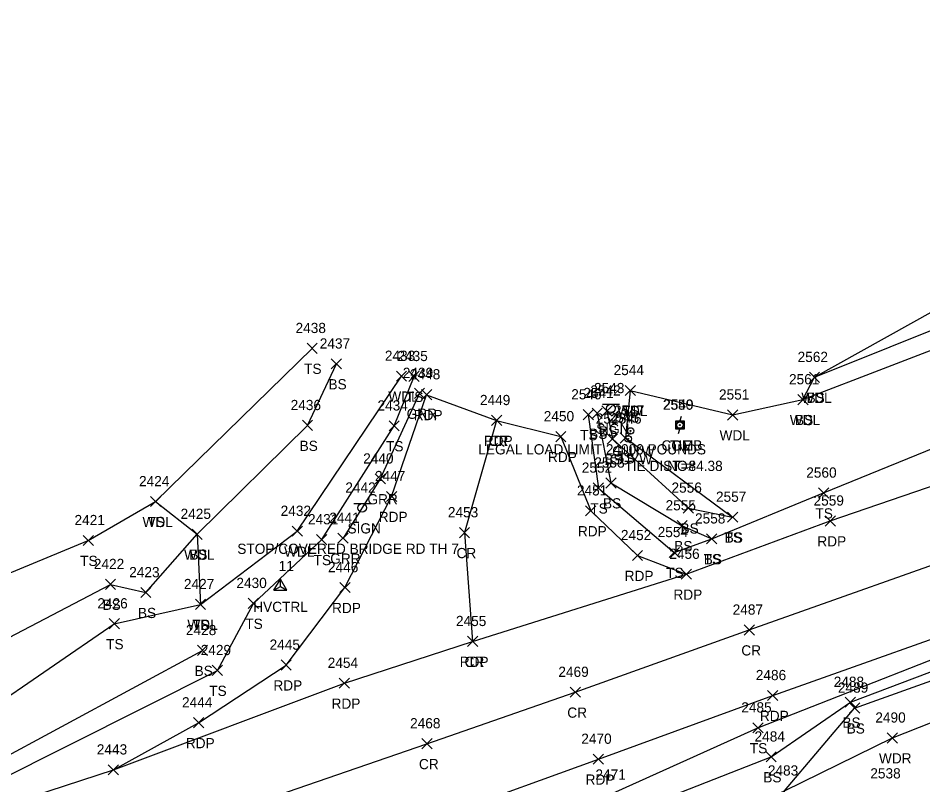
# Model space of a CAD drawing. Extents: x 1699408 to 1700423, y 840176 to 841410.
# Drawn here: x 1700025.1 to 1700202.3, y 840401 to 840551.2 of the extents above; entities that cross this region are included whole.
import ezdxf

# ---------------------------------------------------------------- set-up
doc = ezdxf.new("R2010")
doc.units = 0
for name, color, linetype in [('C_A', 7, 'Continuous'), ('C_C', 7, 'Continuous'), ('C_I', 7, 'Continuous'), ('CBP', 7, 'Continuous'), ('CPSM', 7, 'Continuous'), ('L_A', 7, 'Continuous'), ('L_I', 7, 'Continuous'), ('L_TIC', 7, 'Continuous'), ('LAWA', 7, 'Continuous'), ('LELB', 7, 'Continuous'), ('P_A', 7, 'Continuous'), ('P_I', 7, 'Continuous'), ('P_TIC', 7, 'Continuous'), ('PET', 7, 'Continuous'), ('PRC', 7, 'Continuous'), ('R_A', 7, 'Continuous'), ('R_I', 7, 'Continuous'), ('R_TIC', 7, 'Continuous'), ('RGR', 7, 'Continuous'), ('S_A', 7, 'Continuous'), ('S_C', 7, 'Continuous'), ('S_I', 7, 'Continuous'), ('SSGN', 7, 'Continuous'), ('U_A', 7, 'Continuous'), ('U_C', 7, 'Continuous'), ('U_I', 7, 'Continuous'), ('UP', 7, 'Continuous'), ('UPGW', 7, 'Continuous')]:
    doc.layers.add(name, color=color, linetype=linetype)

msp = doc.modelspace()

# ---------------------------------------------------------------- linework, layer by layer
at = {"layer": 'CBP'}
for radius in [0.625, 0.0833]:
    msp.add_circle((1700154.75, 840471.45), radius, dxfattribs=at)
at = {"layer": 'CPSM'}
for p, q in [((1700075.25, 840439.12), (1700076.5, 840441.29)), ((1700077.75, 840439.12), (1700076.5, 840441.29)), ((1700076.5, 840439.85), (1700076.5, 840441.29)), ((1700075.25, 840439.12), (1700076.5, 840439.85)), ((1700075.25, 840439.12), (1700077.75, 840439.12)), ((1700076.5, 840439.85), (1700076.5, 840439.85)), ((1700076.5, 840439.85), (1700077.75, 840439.12))]:
    msp.add_line(p, q, dxfattribs=at)
at = {"layer": 'L_TIC'}
for points in [[(1700081.74, 840485.47), (1700083.74, 840487.47)], [(1700083.74, 840485.47), (1700081.74, 840487.47)], [(1700086.48, 840482.44), (1700088.48, 840484.44)], [(1700088.48, 840482.44), (1700086.48, 840484.44)], [(1700099.23, 840480.03), (1700101.23, 840482.03)], [(1700101.23, 840480.03), (1700099.23, 840482.03)], [(1700101.69, 840479.98), (1700103.69, 840481.98)], [(1700103.69, 840479.98), (1700101.69, 840481.98)], [(1700180.12, 840479.8), (1700182.12, 840481.8)], [(1700182.12, 840479.8), (1700180.12, 840481.8)], [(1700180.12, 840479.8), (1700182.12, 840481.8)], [(1700182.12, 840479.8), (1700180.12, 840481.8)], [(1700144.03, 840477.23), (1700146.03, 840479.23)], [(1700146.03, 840477.23), (1700144.03, 840479.23)], [(1700144.03, 840477.23), (1700146.03, 840479.23)], [(1700146.03, 840477.23), (1700144.03, 840479.23)], [(1700177.86, 840475.43), (1700179.86, 840477.43)], [(1700179.86, 840475.43), (1700177.86, 840477.43)], [(1700177.86, 840475.43), (1700179.86, 840477.43)], [(1700179.86, 840475.43), (1700177.86, 840477.43)], [(1700135.81, 840472.48), (1700137.81, 840474.48)], [(1700137.81, 840472.48), (1700135.81, 840474.48)], [(1700137.54, 840472.74), (1700139.54, 840474.74)], [(1700139.54, 840472.74), (1700137.54, 840474.74)], [(1700139.47, 840473.22), (1700141.47, 840475.22)], [(1700141.47, 840473.22), (1700139.47, 840475.22)], [(1700164.1, 840472.44), (1700166.1, 840474.44)], [(1700166.1, 840472.44), (1700164.1, 840474.44)], [(1700080.83, 840470.38), (1700082.83, 840472.38)], [(1700082.83, 840470.38), (1700080.83, 840472.38)], [(1700097.79, 840470.3), (1700099.79, 840472.3)], [(1700099.79, 840470.3), (1700097.79, 840472.3)], [(1700140.53, 840467.73), (1700142.53, 840469.73)], [(1700142.53, 840467.73), (1700140.53, 840469.73)], [(1700143.08, 840467.93), (1700145.08, 840469.93)], [(1700145.08, 840467.93), (1700143.08, 840469.93)], [(1700140.25, 840459.12), (1700142.25, 840461.12)], [(1700142.25, 840459.12), (1700140.25, 840461.12)], [(1700137.8, 840458.12), (1700139.8, 840460.12)], [(1700139.8, 840458.12), (1700137.8, 840460.12)], [(1700181.9, 840457.15), (1700183.9, 840459.15)], [(1700183.9, 840457.15), (1700181.9, 840459.15)], [(1700051.08, 840455.47), (1700053.08, 840457.47)], [(1700053.08, 840455.47), (1700051.08, 840457.47)], [(1700051.08, 840455.47), (1700053.08, 840457.47)], [(1700053.08, 840455.47), (1700051.08, 840457.47)], [(1700155.42, 840454.2), (1700157.42, 840456.2)], [(1700157.42, 840454.2), (1700155.42, 840456.2)], [(1700164.08, 840452.42), (1700166.08, 840454.42)], [(1700166.08, 840452.42), (1700164.08, 840454.42)], [(1700164.08, 840452.42), (1700166.08, 840454.42)], [(1700166.08, 840452.42), (1700164.08, 840454.42)], [(1700078.82, 840449.67), (1700080.82, 840451.67)], [(1700080.82, 840449.67), (1700078.82, 840451.67)], [(1700154.21, 840450.74), (1700156.21, 840452.74)], [(1700156.21, 840450.74), (1700154.21, 840452.74)], [(1700037.88, 840447.85), (1700039.88, 840449.85)], [(1700039.88, 840447.85), (1700037.88, 840449.85)], [(1700059.22, 840449.07), (1700061.22, 840451.07)], [(1700061.22, 840449.07), (1700059.22, 840451.07)], [(1700059.22, 840449.07), (1700061.22, 840451.07)], [(1700061.22, 840449.07), (1700059.22, 840451.07)], [(1700083.61, 840448.01), (1700085.61, 840450.01)], [(1700085.61, 840448.01), (1700083.61, 840450.01)], [(1700159.98, 840448.17), (1700161.98, 840450.17)], [(1700161.98, 840448.17), (1700159.98, 840450.17)], [(1700159.98, 840448.17), (1700161.98, 840450.17)], [(1700161.98, 840448.17), (1700159.98, 840450.17)], [(1700152.66, 840445.5), (1700154.66, 840447.5)], [(1700154.66, 840445.5), (1700152.66, 840447.5)], [(1700042.23, 840439.25), (1700044.23, 840441.25)], [(1700044.23, 840439.25), (1700042.23, 840441.25)], [(1700049.16, 840437.65), (1700051.16, 840439.65)], [(1700051.16, 840437.65), (1700049.16, 840439.65)], [(1700059.87, 840435.32), (1700061.87, 840437.32)], [(1700061.87, 840435.32), (1700059.87, 840437.32)], [(1700059.87, 840435.32), (1700061.87, 840437.32)], [(1700061.87, 840435.32), (1700059.87, 840437.32)], [(1700070.23, 840435.53), (1700072.23, 840437.53)], [(1700072.23, 840435.53), (1700070.23, 840437.53)], [(1700042.97, 840431.54), (1700044.97, 840433.54)], [(1700044.97, 840431.54), (1700042.97, 840433.54)], [(1700060.26, 840426.31), (1700062.26, 840428.31)], [(1700062.26, 840426.31), (1700060.26, 840428.31)], [(1700063.16, 840422.4), (1700065.16, 840424.4)], [(1700065.16, 840422.4), (1700063.16, 840424.4)], [(1700187.14, 840416.18), (1700189.14, 840418.18)], [(1700189.14, 840416.18), (1700187.14, 840418.18)], [(1700187.97, 840415.03), (1700189.97, 840417.03)], [(1700189.97, 840415.03), (1700187.97, 840417.03)], [(1700169.04, 840411.16), (1700171.04, 840413.16)], [(1700171.04, 840411.16), (1700169.04, 840413.16)], [(1700195.37, 840409.18), (1700197.37, 840411.18)], [(1700197.37, 840409.18), (1700195.37, 840411.18)], [(1700171.64, 840405.47), (1700173.64, 840407.47)], [(1700173.64, 840405.47), (1700171.64, 840407.47)]]:
    msp.add_lwpolyline(points, dxfattribs=at)
at = {"layer": 'LAWA'}
for points in [[(1700145.03, 840478.23), (1700165.1, 840473.44), (1700178.86, 840476.43), (1700181.12, 840480.8), (1700209.13, 840496.46), (1700243.79, 840518.11), (1700281.69, 840520.84), (1700332.18, 840533.79), (1700369.71, 840547.2), (1700395.55, 840551.16)], [(1700117.89, 840346.79), (1700115.47, 840370.34), (1700134.74, 840381.65), (1700175.24, 840399.81), (1700196.37, 840410.18), (1700227.82, 840422.6), (1700263.02, 840437.63), (1700310.41, 840452.18), (1700348.89, 840465.62), (1700387.69, 840477.37), (1700417.82, 840485.58)], [(1700052.08, 840456.47), (1700060.22, 840450.07), (1700060.87, 840436.32), (1700079.82, 840450.67), (1700100.23, 840481.03)]]:
    msp.add_lwpolyline(points, dxfattribs=at)
at = {"layer": 'LELB'}
for points in [[(1700181.12, 840480.8), (1700210.79, 840492.71), (1700248.16, 840507.11), (1700281.22, 840518.3), (1700334.33, 840530.5), (1700370.69, 840544.36), (1700395.55, 840551.16)], [(1700178.86, 840476.43), (1700212.16, 840489.26), (1700248.63, 840504.95), (1700282.26, 840515.64), (1700334.86, 840528.51), (1700371.4, 840540.85), (1700398.24, 840544.25)], [(1700136.81, 840473.48), (1700138.8, 840459.12), (1700153.66, 840446.5), (1700160.98, 840449.17), (1700182.9, 840458.15), (1700217.68, 840472.32), (1700251.63, 840484.37), (1700288.96, 840496.07), (1700338.68, 840513.45), (1700373.92, 840524.16), (1700400.76, 840534.56)], [(1699894.91, 840318.62), (1699909.54, 840320.37), (1699931.73, 840326.89), (1699942.77, 840330.34), (1699953.04, 840332.24), (1699965.49, 840337.33), (1699971.91, 840344.73), (1700003.63, 840352.88), (1700032.87, 840363), (1700063.25, 840372.76), (1700109.93, 840390.42), (1700140.91, 840399), (1700170.04, 840412.16), (1700222.58, 840432.8), (1700261.59, 840445.7), (1700307.68, 840461.11), (1700347.68, 840474.56), (1700384.18, 840486.92), (1700414.06, 840495.99)], [(1699950.19, 840322.46), (1699970.52, 840330.95), (1699975.9, 840338.67), (1700003.21, 840345.94), (1700034.35, 840356.49), (1700066.22, 840366.04), (1700111.96, 840382.71), (1700172.64, 840406.47), (1700188.14, 840417.18), (1700223.53, 840430.55), (1700261.76, 840444.29), (1700308.01, 840458.93), (1700347.92, 840472.31), (1700385.46, 840483.48), (1700416.04, 840491.19)], [(1700177.27, 840387.2), (1700175.24, 840399.81), (1700188.97, 840416.03), (1700224.35, 840428.66), (1700261.3, 840441.34), (1700309.36, 840456.05), (1700348.46, 840469.98), (1700386.66, 840479.73), (1700417.03, 840487.78)], [(1699978.99, 840419.52), (1699997.35, 840429.46), (1700012, 840437.76), (1700038.88, 840448.85), (1700052.08, 840456.47), (1700082.74, 840486.47)], [(1699973.36, 840411.5), (1700000.19, 840415.42), (1700014.72, 840425.34), (1700043.23, 840440.25), (1700050.16, 840438.65), (1700060.22, 840450.07), (1700081.83, 840471.38), (1700087.48, 840483.44)], [(1699979.47, 840387.15), (1700008.42, 840397.8), (1700020.57, 840401.5), (1700064.16, 840423.4), (1700071.23, 840436.53), (1700084.61, 840449.01), (1700098.79, 840471.3), (1700102.69, 840480.98)], [(1700145.03, 840478.23), (1700144.08, 840468.93), (1700165.08, 840453.42)], [(1700138.54, 840473.74), (1700141.25, 840460.12), (1700155.21, 840451.74), (1700160.98, 840449.17)], [(1700140.47, 840474.22), (1700141.53, 840468.73), (1700156.42, 840455.2), (1700165.08, 840453.42)], [(1699946.19, 840397.92), (1699957.68, 840405.42), (1699965.5, 840411.31), (1699969.56, 840405.36), (1699976.97, 840400.87), (1700003.92, 840408.68), (1700018.42, 840415.01), (1700043.97, 840432.54), (1700060.87, 840436.32)], [(1699969.68, 840389.69), (1700006.32, 840402.67), (1700019.85, 840404.95), (1700061.26, 840427.31)]]:
    msp.add_lwpolyline(points, dxfattribs=at)
at = {"layer": 'P_TIC'}
for points in [[(1700104.14, 840476.4), (1700106.14, 840478.4)], [(1700106.14, 840476.4), (1700104.14, 840478.4)], [(1700117.86, 840471.36), (1700119.86, 840473.36)], [(1700119.86, 840471.36), (1700117.86, 840473.36)], [(1700117.86, 840471.36), (1700119.86, 840473.36)], [(1700119.86, 840471.36), (1700117.86, 840473.36)], [(1700130.44, 840468.19), (1700132.44, 840470.19)], [(1700132.44, 840468.19), (1700130.44, 840470.19)], [(1700097.29, 840456.47), (1700099.29, 840458.47)], [(1700099.29, 840456.47), (1700097.29, 840458.47)], [(1700136.28, 840453.66), (1700138.28, 840455.66)], [(1700138.28, 840453.66), (1700136.28, 840455.66)], [(1700183.2, 840451.68), (1700185.2, 840453.68)], [(1700185.2, 840451.68), (1700183.2, 840453.68)], [(1700111.57, 840449.38), (1700113.57, 840451.38)], [(1700113.57, 840449.38), (1700111.57, 840451.38)], [(1700145.46, 840444.91), (1700147.46, 840446.91)], [(1700147.46, 840444.91), (1700145.46, 840446.91)], [(1700155, 840441.24), (1700157, 840443.24)], [(1700157, 840441.24), (1700155, 840443.24)], [(1700155, 840441.24), (1700157, 840443.24)], [(1700157, 840441.24), (1700155, 840443.24)], [(1700088.15, 840438.63), (1700090.15, 840440.63)], [(1700090.15, 840438.63), (1700088.15, 840440.63)], [(1700167.35, 840430.32), (1700169.35, 840432.32)], [(1700169.35, 840430.32), (1700167.35, 840432.32)], [(1700113.15, 840428.08), (1700115.15, 840430.08)], [(1700115.15, 840428.08), (1700113.15, 840430.08)], [(1700113.15, 840428.08), (1700115.15, 840430.08)], [(1700115.15, 840428.08), (1700113.15, 840430.08)], [(1700076.65, 840423.45), (1700078.65, 840425.45)], [(1700078.65, 840423.45), (1700076.65, 840425.45)], [(1700088.04, 840419.89), (1700090.04, 840421.89)], [(1700090.04, 840419.89), (1700088.04, 840421.89)], [(1700133.27, 840418.13), (1700135.27, 840420.13)], [(1700135.27, 840418.13), (1700133.27, 840420.13)], [(1700171.93, 840417.49), (1700173.93, 840419.49)], [(1700173.93, 840417.49), (1700171.93, 840419.49)], [(1700059.5, 840412.15), (1700061.5, 840414.15)], [(1700061.5, 840412.15), (1700059.5, 840414.15)], [(1700104.22, 840408.05), (1700106.22, 840410.05)], [(1700106.22, 840408.05), (1700104.22, 840410.05)], [(1700137.79, 840405.02), (1700139.79, 840407.02)], [(1700139.79, 840405.02), (1700137.79, 840407.02)], [(1700042.81, 840402.93), (1700044.81, 840404.93)], [(1700044.81, 840402.93), (1700042.81, 840404.93)], [(1700042.81, 840402.93), (1700044.81, 840404.93)], [(1700044.81, 840402.93), (1700042.81, 840404.93)]]:
    msp.add_lwpolyline(points, dxfattribs=at)
at = {"layer": 'PET'}
for points in [[(1700021.62, 840396.71), (1700043.81, 840403.93), (1700089.04, 840420.89), (1700114.15, 840429.08), (1700156, 840442.24), (1700184.2, 840452.68), (1700219.84, 840464.9), (1700253.86, 840476.91), (1700292.78, 840490.43), (1700340.75, 840506.36), (1700375.21, 840518.2), (1700402.6, 840527.14)], [(1700000.7, 840359.42), (1700031.35, 840369.03), (1700061.33, 840378.61), (1700109.24, 840395.28), (1700138.79, 840406.02), (1700172.93, 840418.49), (1700221.46, 840435.72), (1700260.32, 840448.69), (1700306.34, 840464.7), (1700346.69, 840478.05), (1700382.8, 840490.67), (1700413.01, 840500.61)], [(1700043.81, 840403.93), (1700060.5, 840413.15), (1700077.65, 840424.45), (1700089.15, 840439.63), (1700098.29, 840457.47), (1700105.14, 840477.4), (1700118.86, 840472.36), (1700131.44, 840469.19), (1700137.28, 840454.66), (1700146.46, 840445.91), (1700156, 840442.24)]]:
    msp.add_lwpolyline(points, dxfattribs=at)
at = {"layer": 'PRC'}
for points in [[(1699996.81, 840372.51), (1700026.94, 840382.38), (1700056.52, 840392.21), (1700105.22, 840409.05), (1700134.27, 840419.13), (1700168.35, 840431.32), (1700216.93, 840448.55), (1700256.68, 840462.13), (1700302.17, 840477.7), (1700342.85, 840491.54), (1700378.3, 840503.62), (1700408.52, 840513.62)], [(1700118.86, 840472.36), (1700112.57, 840450.38), (1700114.15, 840429.08)]]:
    msp.add_lwpolyline(points, dxfattribs=at)
at = {"layer": 'R_TIC'}
for points in [[(1700102.75, 840476.67), (1700104.75, 840478.67)], [(1700104.75, 840476.67), (1700102.75, 840478.67)], [(1700095.07, 840459.92), (1700097.07, 840461.92)], [(1700097.07, 840459.92), (1700095.07, 840461.92)], [(1700087.78, 840448.3), (1700089.78, 840450.3)], [(1700089.78, 840448.3), (1700087.78, 840450.3)]]:
    msp.add_lwpolyline(points, dxfattribs=at)
at = {"layer": 'RGR'}
msp.add_lwpolyline([(1700103.75, 840477.67), (1700096.07, 840460.92), (1700088.78, 840449.3)], dxfattribs=at)
at = {"layer": 'SSGN'}
for p, q in [((1700139.57, 840475.55), (1700142.91, 840475.55)), ((1700141.22, 840474.72), (1700141.22, 840474.72)), ((1700090.87, 840456.08), (1700094.2, 840456.08)), ((1700092.51, 840455.24), (1700092.51, 840455.24))]:
    msp.add_line(p, q, dxfattribs=at)
for centre in [(1700141.22, 840474.72), (1700092.51, 840455.24)]:
    msp.add_circle(centre, 0.833, dxfattribs=at)
at = {"layer": 'UP'}
for p, q in [((1700155.01, 840473.13), (1700154.76, 840472.3)), ((1700153.93, 840470.63), (1700153.93, 840472.3)), ((1700153.93, 840472.3), (1700155.59, 840472.3)), ((1700154.76, 840471.46), (1700154.76, 840471.46)), ((1700155.59, 840472.3), (1700155.59, 840470.63)), ((1700155.59, 840470.63), (1700153.93, 840470.63)), ((1700154.51, 840469.8), (1700154.76, 840470.63))]:
    msp.add_line(p, q, dxfattribs=at)
msp.add_circle((1700154.76, 840471.46), 0.833, dxfattribs=at)
at = {"layer": 'UPGW'}
for centre, radius in [((1700145.1, 840470.3), 0.625), ((1700144.62, 840468.74), 0.625), ((1700145.1, 840470.3), 0.0833), ((1700144.62, 840468.74), 0.0833)]:
    msp.add_circle(centre, radius, dxfattribs=at)

# ---------------------------------------------------------------- texts
at = {"layer": 'C_A'}
for s, p in [('TIE', (1700152.83, 840466.45)), ('HVCTRL', (1700071.19, 840434.85))]:
    msp.add_text(s, height=2, dxfattribs=at).set_placement(p)
at = {"layer": 'C_C'}
msp.add_text('TIE DIST=84.38', height=2, dxfattribs=at).set_placement((1700143.89, 840462.45))
at = {"layer": 'C_I'}
for s, p in [('2550', (1700151.41, 840474.45)), ('11', (1700076.17, 840442.85))]:
    msp.add_text(s, height=2, dxfattribs=at).set_placement(p)
at = {"layer": 'L_A'}
for s, p in [('TS', (1700081.15, 840481.47)), ('BS', (1700085.92, 840478.44)), ('WDL', (1700097.65, 840476.03)), ('TS', (1700101.1, 840475.98)), ('WDL', (1700178.54, 840475.8)), ('BS', (1700179.56, 840475.8)), ('WDL', (1700142.45, 840473.23)), ('TS', (1700143.44, 840473.23)), ('WDL', (1700176.28, 840471.43)), ('BS', (1700177.3, 840471.43)), ('BS', (1700136.98, 840468.74)), ('BS', (1700138.91, 840469.22)), ('TS', (1700135.22, 840468.48)), ('WDL', (1700162.52, 840468.44)), ('BS', (1700080.27, 840466.38)), ('TS', (1700097.2, 840466.3)), ('BS', (1700139.97, 840463.73)), ('TS', (1700142.49, 840463.93)), ('BS', (1700139.69, 840455.12)), ('TS', (1700137.21, 840454.12)), ('TS', (1700181.3, 840453.15)), ('WDL', (1700049.5, 840451.47)), ('TS', (1700050.49, 840451.47)), ('BS', (1700154.87, 840450.2)), ('TS', (1700163.49, 840448.42)), ('BS', (1700163.53, 840448.42)), ('BS', (1700153.65, 840446.74)), ('WDL', (1700057.64, 840445.07)), ('BS', (1700058.66, 840445.07)), ('WDL', (1700077.24, 840445.67)), ('TS', (1700083.01, 840444.01)), ('TS', (1700159.39, 840444.17)), ('BS', (1700159.42, 840444.17)), ('TS', (1700037.29, 840443.85)), ('TS', (1700152.07, 840441.5)), ('BS', (1700041.68, 840435.25)), ('BS', (1700048.6, 840433.65)), ('TS', (1700069.64, 840431.53)), ('WDL', (1700058.29, 840431.32)), ('TS', (1700059.28, 840431.32)), ('TS', (1700042.38, 840427.54)), ('BS', (1700059.7, 840422.31)), ('TS', (1700062.57, 840418.4)), ('BS', (1700186.58, 840412.18)), ('BS', (1700187.41, 840411.03)), ('TS', (1700168.45, 840407.16)), ('WDR', (1700193.74, 840405.18)), ('BS', (1700171.09, 840401.47))]:
    msp.add_text(s, height=2, dxfattribs=at).set_placement(p)
at = {"layer": 'L_I'}
for s, p in [('2438', (1700079.48, 840489.47)), ('2437', (1700084.22, 840486.44)), ('2433', (1700096.97, 840484.03)), ('2435', (1700099.43, 840483.98)), ('2562', (1700177.81, 840483.8)), ('2562', (1700177.81, 840483.8)), ('2544', (1700141.77, 840481.23)), ('2544', (1700141.77, 840481.23)), ('2561', (1700176.12, 840479.43)), ('2561', (1700176.12, 840479.43)), ('2540', (1700133.47, 840476.48)), ('2541', (1700135.84, 840476.74)), ('2542', (1700137.21, 840477.22)), ('2551', (1700162.41, 840476.44)), ('2436', (1700078.52, 840474.38)), ('2434', (1700095.53, 840474.3)), ('2548', (1700138.27, 840471.73)), ('2545', (1700140.82, 840471.93)), ('2552', (1700135.54, 840462.12)), ('2553', (1700137.99, 840463.12)), ('2560', (1700179.5, 840461.15)), ('2424', (1700048.82, 840459.47)), ('2424', (1700048.82, 840459.47)), ('2556', (1700153.11, 840458.2)), ('2557', (1700161.82, 840456.42)), ('2557', (1700161.82, 840456.42)), ('2555', (1700151.95, 840454.74)), ('2425', (1700056.96, 840453.07)), ('2425', (1700056.96, 840453.07)), ('2432', (1700076.56, 840453.67)), ('2421', (1700036.18, 840451.85)), ('2431', (1700081.91, 840452.01)), ('2558', (1700157.72, 840452.17)), ('2558', (1700157.72, 840452.17)), ('2554', (1700150.4, 840449.5)), ('2422', (1700039.97, 840443.25)), ('2423', (1700046.9, 840441.65)), ('2427', (1700057.61, 840439.32)), ('2427', (1700057.61, 840439.32)), ('2430', (1700067.89, 840439.53)), ('2426', (1700040.66, 840435.54)), ('2428', (1700058, 840430.31)), ('2429', (1700060.9, 840426.4)), ('2488', (1700184.88, 840420.18)), ('2489', (1700185.7, 840419.03)), ('2485', (1700166.78, 840415.16)), ('2490', (1700193.03, 840413.18)), ('2484', (1700169.38, 840409.47)), ('2471', (1700138.21, 840402)), ('2483', (1700171.98, 840402.81)), ('2483', (1700171.98, 840402.81)), ('2538', (1700192.05, 840402.24))]:
    msp.add_text(s, height=2, dxfattribs=at).set_placement(p)
at = {"layer": 'P_A'}
for s, p in [('RDP', (1700102.63, 840472.4)), ('RDP', (1700116.35, 840467.36)), ('CR', (1700117.29, 840467.36)), ('RDP', (1700128.92, 840464.19)), ('RDP', (1700095.77, 840452.47)), ('RDP', (1700134.77, 840449.66)), ('RDP', (1700181.68, 840447.68)), ('CR', (1700111, 840445.38)), ('RDP', (1700143.94, 840440.91)), ('RDP', (1700153.49, 840437.24)), ('RDP', (1700153.49, 840437.24)), ('RDP', (1700086.63, 840434.63)), ('CR', (1700166.79, 840426.32)), ('RDP', (1700111.64, 840424.08)), ('CR', (1700112.58, 840424.08)), ('RDP', (1700075.14, 840419.45)), ('RDP', (1700086.53, 840415.89)), ('CR', (1700132.7, 840414.13)), ('RDP', (1700170.42, 840413.49)), ('RDP', (1700057.99, 840408.15)), ('CR', (1700103.65, 840404.05)), ('RDP', (1700136.28, 840401.02))]:
    msp.add_text(s, height=2, dxfattribs=at).set_placement(p)
at = {"layer": 'P_I'}
for s, p in [('2448', (1700101.88, 840480.4)), ('2449', (1700115.59, 840475.36)), ('2449', (1700115.59, 840475.36)), ('2450', (1700128.09, 840472.19)), ('2447', (1700095.03, 840460.47)), ('2451', (1700134.59, 840457.66)), ('2559', (1700180.93, 840455.68)), ('2453', (1700109.31, 840453.38)), ('2452', (1700143.2, 840448.91)), ('2456', (1700152.68, 840445.24)), ('2456', (1700152.68, 840445.24)), ('2446', (1700085.83, 840442.63)), ('2487', (1700165.09, 840434.32)), ('2455', (1700110.89, 840432.08)), ('2455', (1700110.89, 840432.08)), ('2445', (1700074.39, 840427.45)), ('2454', (1700085.78, 840423.89)), ('2469', (1700130.95, 840422.13)), ('2486', (1700169.62, 840421.49)), ('2444', (1700057.24, 840416.15)), ('2468', (1700101.91, 840412.05)), ('2470', (1700135.44, 840409.02)), ('2443', (1700040.55, 840406.93)), ('2443', (1700040.55, 840406.93))]:
    msp.add_text(s, height=2, dxfattribs=at).set_placement(p)
at = {"layer": 'R_A'}
for p in [(1700101.24, 840472.67), (1700093.56, 840455.92), (1700086.27, 840444.3)]:
    msp.add_text('GRR', height=2, dxfattribs=at).set_placement(p)
at = {"layer": 'R_I'}
for s, p in [('2439', (1700100.48, 840480.67)), ('2440', (1700092.72, 840463.92)), ('2441', (1700086.09, 840452.3))]:
    msp.add_text(s, height=2, dxfattribs=at).set_placement(p)
at = {"layer": 'S_A'}
for p in [(1700138.36, 840469.7), (1700089.65, 840450.22)]:
    msp.add_text('SIGN', height=2, dxfattribs=at).set_placement(p)
at = {"layer": 'S_C'}
for s, p in [('LEGAL LOAD LIMIT 24000 POUNDS', (1700115.28, 840465.7)), ('STOP/COVERED BRIDGE RD TH 7', (1700068.07, 840446.22))]:
    msp.add_text(s, height=2, dxfattribs=at).set_placement(p)
at = {"layer": 'S_I'}
for s, p in [('2543', (1700137.94, 840477.7)), ('2442', (1700089.23, 840458.22))]:
    msp.add_text(s, height=2, dxfattribs=at).set_placement(p)
at = {"layer": 'U_A'}
for s, p in [('GUYW', (1700141.49, 840465.3)), ('COMB', (1700151.15, 840466.46)), ('GUYW', (1700141.01, 840463.74))]:
    msp.add_text(s, height=2, dxfattribs=at).set_placement(p)
at = {"layer": 'U_C'}
msp.add_text('NO#', height=2, dxfattribs=at).set_placement((1700152.27, 840462.46))
at = {"layer": 'U_I'}
for s, p in [('2549', (1700151.49, 840474.46)), ('2547', (1700141.84, 840473.3)), ('2546', (1700141.3, 840471.74))]:
    msp.add_text(s, height=2, dxfattribs=at).set_placement(p)

doc.saveas('drawing.dxf')
